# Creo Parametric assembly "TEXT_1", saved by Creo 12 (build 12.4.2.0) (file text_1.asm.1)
Units: Custom; MM, KILOGRAM, SECS

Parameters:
  PTC_WM_ITERATION = "0"
  PTC_WM_VERSION = "-.0"
  PTC_WM_LIFECYCLE_STATE = "In Work"
  PTC_WM_LIFECYCLE = "MO_CADDocument"
  PTC_WM_CREATED_BY = "Maximilian Roepper (Z0017RMS: MO)"
  PTC_WM_CREATED_ON = "18-Sep-26 11:36:42 AM"
  PTC_WM_MODIFIED_BY = "Maximilian Roepper (Z0017RMS: MO)"
  PTC_WM_MODIFIED_ON = "18-Sep-26 11:36:46 AM"
  PDMLINKNUMBER = "PDM000071454828"
  PTC_WM_NUMBER = "PDM000071454828"

Other parameters: WEIGHT, WEIGHT_FACTOR, WEIGHT_ADD, MC_ERRORS, SUPPLIER

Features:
  1. coordinate system
  2. imported feature
  3. component "SHAPESTRING114_1"
  4. component "SHAPESTRING118_1"
  5. component "SHAPESTRING123_1"
  6. component "SHAPESTRING127_1"
  7. component "SHAPESTRING132_1"
  8. component "SHAPESTRING141_1"
  9. component "SHAPESTRING144_1"
  10. component "SHAPESTRING147_1"
  11. component "SHAPESTRING156_1"
  12. component "SHAPESTRING158_1"
  13. component "SHAPESTRING163_1"
  14. component "SHAPESTRING165_1"
  15. component "SHAPESTRING168_1"
  16. component "SHAPESTRING171_1"
  17. component "SHAPESTRING177_1"
  18. component "SHAPESTRING184_1"
  19. component "SHAPESTRING191_1"
  20. component "SHAPESTRING196_1"
  21. component "SHAPESTRING222_1"
  22. component "SHAPESTRING224_1"
  23. component "SHAPESTRING226_1"
  24. component "SHAPESTRING228_1"
  25. component "SHAPESTRING230_1"
  26. component "SHAPESTRING232_1"
  27. component "SHAPESTRING234_1"
  28. component "SHAPESTRING236_1"
  29. component "SHAPESTRING238_1"
  30. component "SHAPESTRING240_1"
  31. component "SHAPESTRING242_1"
  32. component "SHAPESTRING244_1"
  33. component "SHAPESTRING246_1"

Other named items: DRW_VIEW_ORG, ROUGH-GROB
